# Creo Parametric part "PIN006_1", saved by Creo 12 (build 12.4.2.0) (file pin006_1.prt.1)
Units: Custom; MM, KILOGRAM, SECS

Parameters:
  PTC_WM_ITERATION = "0"
  PTC_WM_VERSION = "-.0"
  PTC_WM_LIFECYCLE_STATE = "In Work"
  PTC_WM_LIFECYCLE = "MO_CADDocument"
  PTC_WM_CREATED_BY = "Maximilian Roepper (Z0017RMS: MO)"
  PTC_WM_CREATED_ON = "18-Sep-26 11:36:42 AM"
  PTC_WM_MODIFIED_BY = "Maximilian Roepper (Z0017RMS: MO)"
  PTC_WM_MODIFIED_ON = "18-Sep-26 11:36:46 AM"
  PDMLINKNUMBER = "PDM000071455030"
  PTC_WM_NAME = "pin006_1.prt"
  PTC_WM_NUMBER = "PDM000071455030"

Other parameters: WEIGHT, WEIGHT_FACTOR, WEIGHT_ADD, _MASS_TEMP, _DIFF_TEMP, MC_ERRORS, SUPPLIER

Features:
  1. coordinate system
  2. datum plane "PRT_YZ"
  3. datum plane "PRT_XY"
  4. datum plane "PRT_XZ"
  5. coordinate system
  6. datum axis
  7. datum axis
  8. datum axis
  9. coordinate system
  10. imported feature

Other named items: PRT, SIEMENS_MO, DRW_VIEW_ORG, PRT_X, PRT_Y, PRT_Z, CS0, ROUGH_GROB

Layers: 00_STD_CSYS-KSYS, 01_STD_PLANES-EBENEN, 02_STD_AXES-ACHSEN, 03_STD_CSYS-KSYS, 24_IMPORT_FEAT-IMPORT_KE

Surfaces: 14 plane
